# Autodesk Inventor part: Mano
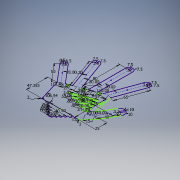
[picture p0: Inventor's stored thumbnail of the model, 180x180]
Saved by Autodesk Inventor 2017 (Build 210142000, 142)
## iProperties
Created: 2017-02
Part Number: Mano
Material: Generic
Document SubType Name: Modeling
Designer: diego
Density: 1 g/cm^3
Appearance: Default
Author: diego
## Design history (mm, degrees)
sketch "Sketch1"
  geometry: L1 (30, 66.923)-(37.103, 136.701); L2 (25.631, 70.051)-(32.464, 137.174); L3 (0, 90.258)-(7.877, 167.638); L4 (17.024, 107.94)-(22.946, 166.104); L5 (-25, 86.342)-(-40.655, 148.265); L6 (-12.624, 86.342)-(-29.022, 151.206); L7 (-34.82, 79.957)-(-51.726, 123.573); L8 (-51.726, 82.098)-(-65.557, 117.783); L9 (38.465, 75.764)-(56.565, 96.92); L10 (46.929, 54.322)-(71.824, 83.991); L11 (46.929, 54.322)-(30, 25); L12 (-30, 25)-(30, 25); L13 (25, 25)-(25, 20); L14 (25, 20)-(-25, 20); L15 (-25, 20)-(-25, 25); L16 (-20, 20)-(-20, 15); L17 (-20, 15)-(20, 15); L18 (20, 15)-(20, 20); L19 (-15, 15)-(-15, 10); L20 (-15, 10)-(15, 10); L21 (15, 10)-(15, 15); L22 (-10, 10)-(-10, 5); L23 (-10, 5)-(10, 5); L24 (10, 5)-(10, 10); L25 (-5, 5)-(-5, 0); L26 (-5, 0)-(5, 0); L27 (5, 0)-(5, 5); L28 (30, 66.923)-(34.445, 64.723); L29 (34.445, 64.723)-(38.465, 75.764); L30 (-51.726, 82.098)-(-47.5, 55.311); L31 (-47.5, 55.311)-(-30, 25); L32 (-34.82, 79.957)-(-25, 86.342); L33 (-12.624, 86.342)-(0, 90.258); L34 (17.024, 107.94)-(25.631, 70.051); A1 r 2.332 centre (34.783, 136.938) between (37.103, 136.701) and (32.464, 137.174); A2 r 7.573 centre (15.411, 166.871) between (22.946, 166.104) and (7.877, 167.638); A3 r 5.999 centre (-34.838, 149.736) between (-29.022, 151.206) and (-40.655, 148.265); A4 r 7.5 centre (-58.564, 120.493) between (-51.726, 123.573) and (-65.557, 117.783); A5 r 10 centre (64.164, 90.419) between (71.824, 83.991) and (56.565, 96.92); 7 further points
  constraints: 68 end point, 10 point on circle, 10 point on line, 9 tangent, 9 vertical, 6 horizontal, 6 midpoint, 5 centre point, 5 parallel, 5 vertical alignment, 1 coincident
  dimensions: "d29" = 50 distance between parallel lines of L13 L15; "d30" = 5 distance of L14.end L15.end; "d31" = 5 distance of L16.start L16.end (= d30); "d32" = 5 distance of L19.start L19.end (= d30); "d33" = 5 distance of L22.start L22.end (= d30); "d34" = 5 distance of L25.start L25.end (= d30); "d35" = 40 distance between parallel lines of L16 L18; "d36" = 30 distance between parallel lines of L21 L19; "d37" = 20 distance between parallel lines of L24 L22; "d38" = 10 distance between parallel lines of L27 L25; "d39" = 60 distance of L12.start L11.end; "d62" = 170 deg angle of L10 L11; "d63" = 10 radius of A5; "d64" = 40 distance of A5.centre L10.start
sketch "Sketch2"
  geometry: L1 (40, -70)-(25.372, 9.235); L2 (25.372, 9.235)-(16.172, 5.886); L3 (-50.743, -18.469)-(-82.883, 19.833); L4 (-25.372, -9.235)-(-49.313, 56.544); L5 (0, 0)-(0, 80); L6 (25.372, 9.235)-(47.603, 70.315); L7 (36.788, -52.604)-(49.718, -45); L8 (49.718, -45)-(69.439, -10.199); L9 (-50.743, -18.469)-(-82.883, 19.833); L10 (-44.243, -16.103)-(-77.903, 24.011); L11 (-87.862, 15.655)-(-55.723, -22.647); L12 (-25.372, -9.235)-(-49.313, 56.544); L13 (-18.324, -6.669)-(-42.265, 59.109); L14 (-56.361, 53.979)-(-32.419, -11.8); L15 (0, 0)-(0, 80); L16 (7.5, 2.73)-(7.5, 80); L17 (-7.5, 80)-(-7.5, -2.73); L18 (25.372, 9.235)-(47.603, 70.315); L19 (32.419, 6.669)-(54.651, 67.749); L20 (40.555, 72.88)-(16.172, 5.886); L21 (36.788, -52.604)-(49.718, -45); L22 (49.718, -45)-(69.439, -10.199); L23 (58.1, -49.839)-(78.099, -15.199); L24 (60.779, -5.199)-(41.954, -37.805); L25 (39.118, -70)-(25, -70); L26 (-25, -70)-(-25, -75); L27 (-25, -75)-(-20, -75); L28 (25, -75)-(25, -70); L29 (-20, -75)-(-20, -80); L30 (-20, -80)-(-15, -80); L31 (20, -80)-(20, -75); L32 (-15, -80)-(-15, -85); L33 (-15, -85)-(-10, -85); L34 (15, -85)-(15, -80); L35 (-10, -85)-(-10, -90); L36 (-10, -90)-(-5, -90); L37 (10, -90)-(10, -85); L38 (-5, -90)-(-5, -95); L39 (-5, -95)-(5, -95); L40 (5, -95)-(5, -90); L41 (-55.723, -22.647)-(-42.082, -68.569); L42 (40.595, -69.348)-(56.866, -51.526); L43 (-55.723, -22.647)-(-50.743, -18.469); L44 (25.372, 9.235)-(32.419, 6.669); L45 (7.5, 2.73)-(-7.5, -2.73); L46 (-18.324, -6.669)-(-32.419, -11.8); L47 (-44.243, -16.103)-(-50.743, -18.469); L48 (-83.955, 18.933)-(-81.81, 20.733); L49 (-83.955, 18.933)-(-88.035, 23.796); L50 (-81.81, 20.733)-(-85.89, 25.595); L51 (-50.676, 56.048)-(-47.951, 57.04); L52 (-47.951, 57.04)-(-50.467, 63.955); L53 (-50.676, 56.048)-(-53.192, 62.963); L54 (-1.5, 80)-(1.5, 80); L55 (1.5, 80)-(1.5, 87.348); L56 (-1.5, 80)-(-1.5, 87.348); L57 (46.146, 70.845)-(49.06, 69.784); L58 (49.06, 69.784)-(51.569, 76.68); L59 (46.146, 70.845)-(48.656, 77.74); L60 (-39.756, -18.951)-(-36.906, -18.951); L61 (-36.906, -18.951)-(-36.906, -13.433); L62 (-39.756, -18.951)-(-39.756, -14.47); L63 (-14.387, -5.236)-(-14.387, -9.7); L64 (-14.387, -9.7)-(-11.437, -9.7)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; A1 r 2 centre (-40.165, -68) between (-42.082, -68.569) and (-40.165, -70); A2 r 9.679 centre (49.718, -45) between (56.866, -51.526) and (58.1, -49.839); A3 r 9.679 centre (49.718, -45) between (56.866, -51.526) and (58.1, -49.839); A4 r 2 centre (39.118, -68) between (39.118, -70) and (40.595, -69.348); A5 r 6.5 centre (-82.883, 19.833) between (-77.903, 24.011) and (-85.89, 25.595); A6 r 6.5 centre (-82.883, 19.833) between (-88.035, 23.796) and (-87.862, 15.655); A7 r 7.5 centre (-49.313, 56.544) between (-42.265, 59.109) and (-50.467, 63.955); A8 r 7.5 centre (-49.313, 56.544) between (-53.192, 62.963) and (-56.361, 53.979); A9 r 7.5 centre (0, 80) between (7.5, 80) and (1.5, 87.348); A10 r 7.5 centre (0, 80) between (-1.5, 87.348) and (-7.5, 80); A11 r 7.5 centre (47.603, 70.315) between (54.651, 67.749) and (51.569, 76.68); A12 r 7.5 centre (47.603, 70.315) between (48.656, 77.74) and (40.555, 72.88); A13 r 10 centre (69.439, -10.199) between (78.099, -15.199) and (75.698, -2.4); A14 r 10 centre (69.439, -10.199) between (72.914, -0.823) and (60.779, -5.199); 17 further points
  constraints: 226 end point, 28 point on circle, 25 perpendicular, 22 parallel, 19 midpoint, 18 tangent, 16 point on line, 15 collinear, 14 centre point, 10 horizontal, 5 vertical alignment, 2 vertical, 1 coincident
  dimensions: "d66" = 80 distance of L5.end L5.start; "d69" = 27 distance of L5.start L1.end; "d70" = 27 distance of L4.start L5.start; "d71" = 20 deg angle of L5 L6; "d72" = 20 deg angle of L4 L5; "d73" = 20 deg angle of L3 L4; "d74" = 65 distance of L6.end L1.end; "d75" = 70 distance of L4.end L4.start; "d76" = 50 distance of L3.end L3.start; "d77" = 70 deg angle of L1 L7; "d78" = 40 distance of L8.end L7.end; "d85" = 70 deg angle of L5 L2; "d87" = 150 deg angle of L8 L7; "d90" = 15 distance of L7.end L7.start; "d92" = 50 distance of L25.end L26.start; "d94" = 40 distance between parallel lines of L29 L31; "d95" = 30 distance between parallel lines of L32 L34; "d96" = 20 distance between parallel lines of L35 L37; "d97" = 10 distance between parallel lines of L38 L40; "d104" = 2 radius of A1 (derived); "d105" = 70 distance from line of L25 L5.start; "d106" = 106.543 deg angle of L41 L25; "d107" = 113.457 deg angle of L41 L43; "d111" = 2 radius of A4 (derived); "d112" = 15 distance from line of L28 L1.start; "d114" = 47.35279 distance from line of L25 L11.end; "d115" = 27 distance of L3.start L4.start; "d116" = 2.8 distance of L48.start L48.end; "d117" = 6.5 radius of A6; "d118" = 6.5 radius of A5 (derived); "d119" = 2.9 distance of L51.start L51.end; "d120" = 7.5 radius of A8; "d121" = 7.5 radius of A7; "d122" = 3 distance of L54.start L54.end; "d123" = 7.5 radius of A9; "d124" = 7.5 radius of A10; "d125" = 3.1 distance between parallel lines of L59 L58; "d126" = 7.5 radius of A12; "d127" = 7.5 radius of A11 (derived); "d128" = 2.85 distance between parallel lines of L61 L62; "d129" = 5 distance from line of point (-38.331, -13.951) L60; "d130" = 5 distance from line of point (-12.912, -4.7) L64; "d131" = 2.95 distance of L63.end L64.end; "d132" = 5 distance from line of point (11.836, 4.308) L67; "d133" = 3.05 distance of L66.end L67.end; "d140" = 3.15 distance between parallel lines of L70 L69; "d143" = 5 distance of L26.start L26.end; "d144" = 5 distance of L27.end L29.end (derived); "d145" = 5 distance of L30.end L32.end (derived); "d146" = 5 distance of L33.end L35.end (derived); "d147" = 5 distance of L36.end L38.end (derived); "d148" = 5 distance of L26.end L27.end; "d149" = 5 distance of L29.end L30.end; "d150" = 5 distance of L32.end L33.end; "d151" = 5 distance of L35.end L36.end; "d152" = 25 distance from line of L25 L7.end; "d153" = 69.43922 horizontal distance of L8.end L5.start; "d154" = 3.2 distance of L77.end L78.end; "d155" = 10 radius of A13; "d156" = 10 radius of A14 (derived); "d157" = 20 vertical distance of L70.start L5.start; "d163" = 50.02 distance between parallel lines of L99 L98; "d164" = 20 distance of L5.start point (0, -20); "d165" = 5 distance between parallel lines of L89 L91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
other parameters: "d79" = 13, "d80" = 15, "d81" = 15, "d82" = 15, "d108" = 25.81341, "d109" = 7.34785, "d113" = 21.31048, "d139" = 135 deg
